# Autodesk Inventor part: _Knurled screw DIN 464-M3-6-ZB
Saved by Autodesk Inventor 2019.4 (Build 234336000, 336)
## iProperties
Created: 2021-08
Part Number: _Knurled screw DIN 464-M3-6-ZB
Material: Generic
Document SubType Name: Modeling
Designer: Administrator
Density: 1 g/cm^3
Appearance: Default
Title: _Knurled screw DIN 464-M3-6-ZB
Author: Administrator
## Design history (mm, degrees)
feature "Body2"
body "Solid1"
